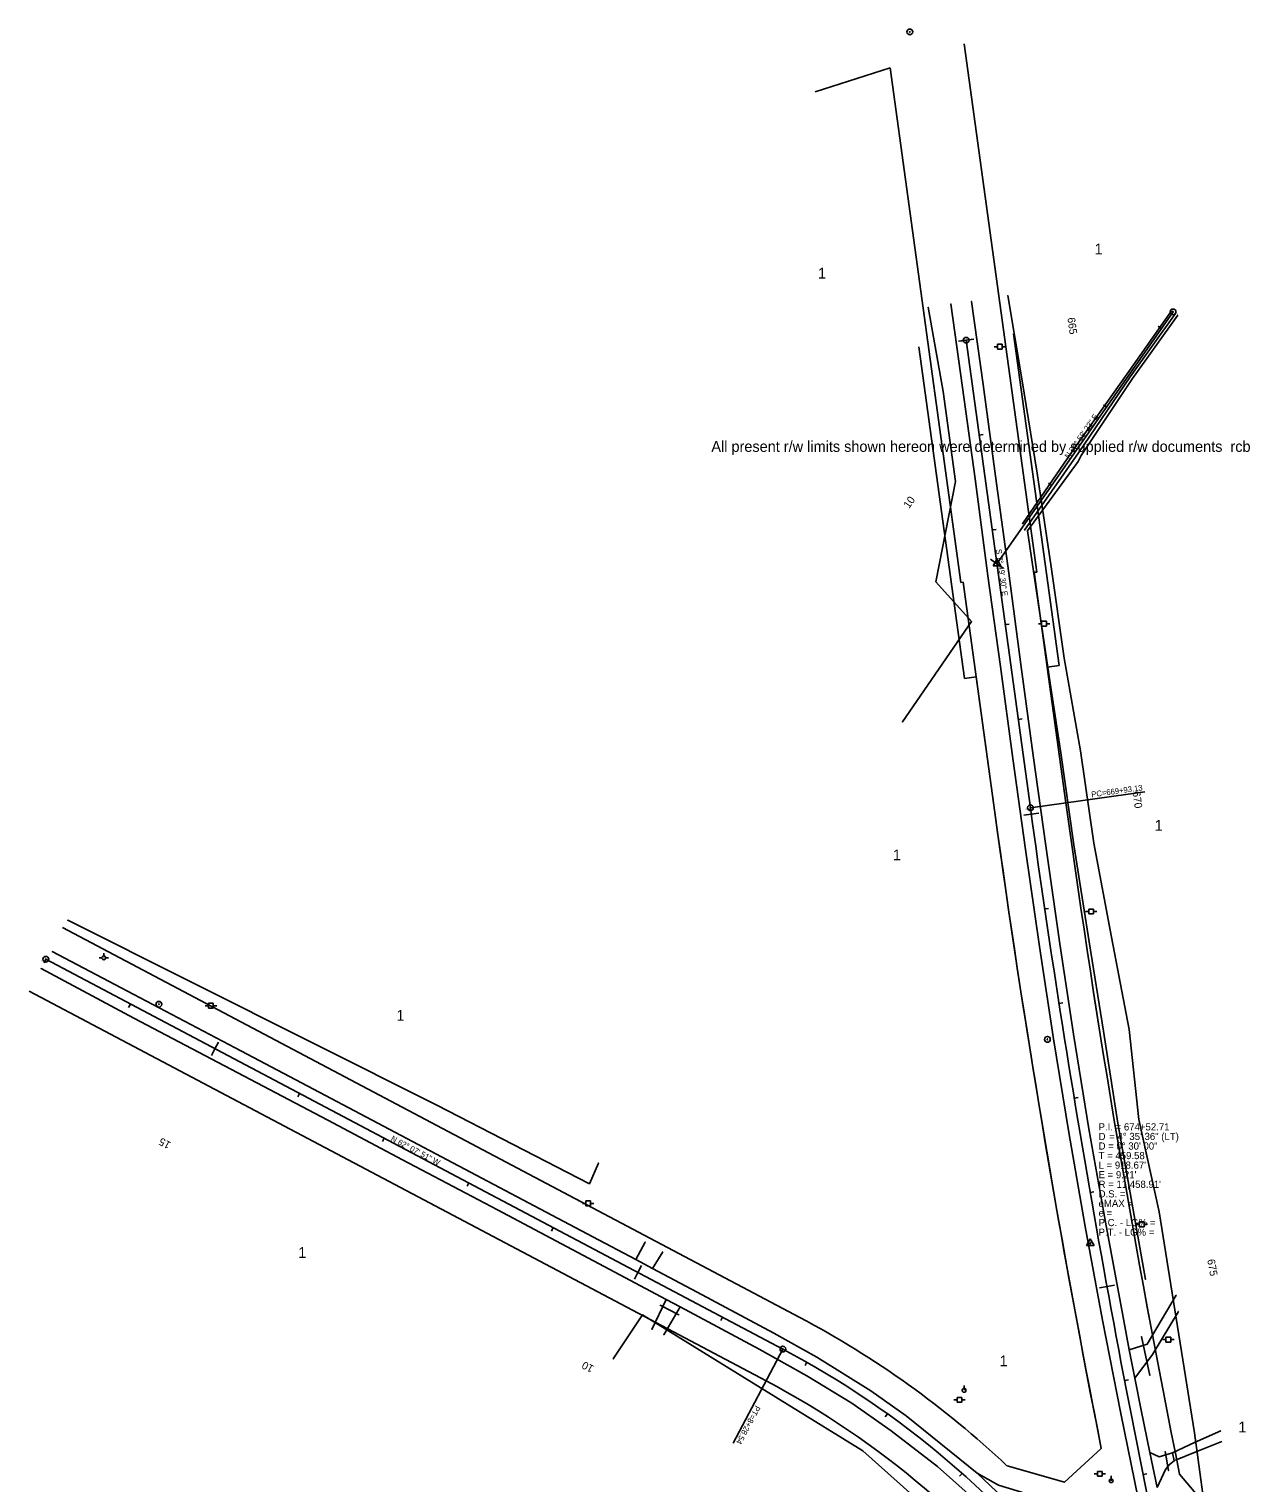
# Model space of a CAD drawing. Extents: x 2519952 to 2531965, y 848341 to 887632.
# Drawn here: x 2529614 to 2530890, y 853383 to 854902 of the extents above; entities that cross this region are included whole.
import ezdxf

# ---------------------------------------------------------------- set-up
doc = ezdxf.new("R2010")
doc.units = 0
for name, color, linetype in [('RD_EX_DR_Pipe', 7, 'Continuous'), ('RD_EX_Driveway', 7, 'Continuous'), ('RD_EX_DV_Prop', 7, 'Continuous'), ('RD_EX_DV_TX_Prop', 7, 'Continuous'), ('RD_EX_Fence_Other', 7, 'Continuous'), ('RD_EX_H2O', 7, 'Continuous'), ('RD_EX_Road', 7, 'Continuous'), ('RD_EX_RW', 7, 'Continuous'), ('RD_EX_RW_TX', 7, 'Continuous'), ('RD_EX_UT', 7, 'Continuous'), ('RD_EX_VEG', 7, 'Continuous'), ('RD_HC_Cl', 7, 'Continuous'), ('RD_HC_Data', 7, 'Continuous'), ('RD_HC_Data_Tic', 7, 'Continuous'), ('RD_HC_Survey_txCode', 7, 'Continuous'), ('RD_HC_TX_Sta50', 7, 'Continuous'), ('RD_HC_txCode', 7, 'Continuous'), ('RD_SMD_Locator', 7, 'Continuous')]:
    doc.layers.add(name, color=color, linetype=linetype)

msp = doc.modelspace()

# ---------------------------------------------------------------- linework, layer by layer
at = {"layer": 'RD_EX_DR_Pipe'}
for p, q in [((2530293.2, 853558.5), (2530273.6, 853568.5)), ((2530785.4, 853495.1), (2530776.8, 853535.8)), ((2530805, 853395.7), (2530801.5, 853415.5))]:
    msp.add_line(p, q, dxfattribs=at)
at = {"layer": 'RD_EX_Driveway'}
for p, q in [((2530258, 853634.6), (2530248.1, 853616.3)), ((2530265.6, 853606.8), (2530276.3, 853624.2)), ((2530280, 853574.6), (2530265, 853543.2)), ((2530294.6, 853567), (2530277.3, 853537.6))]:
    msp.add_line(p, q, dxfattribs=at)
for points in [[(2530763.7, 853522), (2530782.6, 853527.7), (2530813, 853578.9)], [(2530769.8, 853492.4), (2530788.3, 853516.9), (2530815.2, 853562.1)], [(2530809.1, 853414.4), (2530832.1, 853424.9), (2530859.4, 853437.3)], [(2530812.2, 853406.7), (2530832.7, 853414.9), (2530860.6, 853426.1)], [(2530793.2, 853378), (2530801.7, 853396.7), (2530805.9, 853402), (2530810.8, 853405.8), (2530809, 853414.1), (2530795.2, 853410.2), (2530785.5, 853414.5)]]:
    msp.add_lwpolyline(points, dxfattribs=at)
at = {"layer": 'RD_EX_DV_Prop'}
for p, q in [((2530591.2, 854886.7), (2530667.1, 854334.8)), ((2530435.6, 854836.5), (2530513.9, 854861.8)), ((2530513.9, 854861.8), (2530587.8, 854323.9)), ((2530664.6, 854334.5), (2530667.1, 854334.8)), ((2530664.6, 854334.5), (2530697.7, 854093.6)), ((2530590.3, 854324.3), (2530587.8, 854323.9)), ((2530590.3, 854324.3), (2530623.4, 854083.4)), ((2530419.4, 853555.8), (2529649, 853963.2)), ((2530384.4, 853489.5), (2529614, 853896.9)), ((2530696.3, 853383.6), (2530734.6, 853418.9)), ((2530636.1, 853400.8), (2530696.3, 853383.6)), ((2530816.5, 853392), (2530873.2, 853325.3))]:
    msp.add_line(p, q, dxfattribs=at)
for centre, radius, start, end in [((2542013, 855648.7), 11421.7, 187.82505, 191.39527), ((2542013, 855648.7), 11496.7, 187.82505, 191.18314), ((2529955.5, 852678.5), 992.4, 46.7055, 62.1307), ((2529955.5, 852678.5), 917.4, 12.4185, 62.1307)]:
    msp.add_arc(centre, radius, start, end, dxfattribs=at)
at = {"layer": 'RD_EX_Fence_Other'}
msp.add_lwpolyline([(2530781, 853595.5), (2530751.8, 853758.9), (2530737.1, 853854.9), (2530721.9, 853948.2), (2530705.8, 854049.8), (2530692.2, 854145.7), (2530682.3, 854211.8), (2530657.5, 854377.9), (2530710.3, 854450.3), (2530710.3, 854450.3), (2530713.5, 854456.6), (2530767.2, 854537.2), (2530814.6, 854603.4)], dxfattribs=at)
at = {"layer": 'RD_EX_H2O'}
for points in [[(2530652.2, 854385.2), (2530707.4, 854465.2), (2530761.5, 854541.9), (2530808, 854607.9)], [(2530654.4, 854378.6), (2530710.8, 854459.4), (2530764.7, 854538.9), (2530812.1, 854605.1)]]:
    msp.add_lwpolyline(points, dxfattribs=at)
at = {"layer": 'RD_EX_Road'}
for p, q in [((2530589.4, 854527.6), (2530577.4, 854615)), ((2530611, 854530.8), (2530599.1, 854617.6)), ((2530624.2, 854435.1), (2530611, 854530.8)), ((2530602.7, 854432.2), (2530589.4, 854527.6)), ((2530616.2, 854330.7), (2530602.7, 854432.2)), ((2530637.9, 854333.6), (2530624.2, 854435.1)), ((2530650.7, 854238.3), (2530637.9, 854333.6)), ((2530629.4, 854236.2), (2530616.2, 854330.7)), ((2530642.3, 854139.9), (2530629.4, 854236.2)), ((2530663.5, 854143), (2530650.7, 854238.3)), ((2530655.3, 854044.8), (2530642.3, 854139.9)), ((2530676.5, 854048.6), (2530663.5, 854143)), ((2530670, 853943.5), (2530655.3, 854044.8)), ((2530691.4, 853946.2), (2530676.5, 854048.6)), ((2530684.8, 853846.8), (2530670, 853943.5)), ((2530705.7, 853851.7), (2530691.4, 853946.2)), ((2530721.7, 853752.8), (2530705.7, 853851.7)), ((2530700.6, 853749.2), (2530684.8, 853846.8)), ((2530717.9, 853650.8), (2530700.6, 853749.2)), ((2530739.2, 853655.2), (2530721.7, 853752.8)), ((2530736, 853552.8), (2530717.9, 853650.8)), ((2530757.4, 853555.9), (2530739.2, 853655.2)), ((2530755.2, 853455.3), (2530736, 853552.8)), ((2530763.7, 853522), (2530757.4, 853555.9)), ((2530769.8, 853492.4), (2530763.7, 853522)), ((2530776.3, 853458.9), (2530769.8, 853492.4)), ((2530773, 853366.4), (2530755.2, 853455.3)), ((2530785.5, 853414.5), (2530776.3, 853458.9)), ((2530793.2, 853378), (2530785.5, 853414.5))]:
    msp.add_line(p, q, dxfattribs=at)
for points in [[(2530784.4, 853172.5), (2530741.9, 853238.2), (2530696.4, 853297.5), (2530665.4, 853333.2), (2530632.1, 853367.3), (2530604.8, 853393), (2530530.8, 853453), (2530493.8, 853479.2), (2530437.3, 853514.1), (2530392.4, 853539.3), (2530312.3, 853582.2), (2530265.6, 853606.8), (2530248.1, 853616.3), (2530203.3, 853640.1), (2530111.6, 853688.6), (2530014.7, 853739.6), (2529923.8, 853787.8), (2529829.3, 853837.4), (2529710.3, 853900.2), (2529638.2, 853938.2)], [(2530865.4, 852932.6), (2530846.1, 852991.5), (2530818.3, 853061.6), (2530788.3, 853122.1), (2530782.7, 853132.1), (2530724, 853225.4), (2530679.7, 853283.1), (2530649.1, 853318.6), (2530608, 853360.2), (2530563.3, 853399.9), (2530515, 853437.4), (2530473.9, 853466.1), (2530426.9, 853494.9), (2530377.2, 853522.5), (2530294.6, 853567), (2530280, 853574.6), (2530215.1, 853609.1), (2530103.7, 853668.1), (2530004.2, 853720.5), (2529926.3, 853762), (2529818.4, 853818.7), (2529723.5, 853868.7), (2529626.5, 853920.3)], [(2530773, 853366.4), (2530774.4, 853354.1), (2530767.3, 853348.8), (2530760, 853341.3), (2530677.6, 853365.2), (2530627.1, 853380.5), (2530604.8, 853393)]]:
    msp.add_lwpolyline(points, dxfattribs=at)
at = {"layer": 'RD_EX_RW'}
for p, q in [((2530642.9, 854583.8), (2530690.6, 854237.1)), ((2530543.9, 854570.2), (2530591.5, 854223.5)), ((2530678.2, 854235.4), (2530690.6, 854237.1)), ((2530678.2, 854235.4), (2530697.7, 854093.6)), ((2530591.5, 854223.5), (2530603.9, 854225.2)), ((2530603.9, 854225.2), (2530623.4, 854083.4)), ((2530419.4, 853555.8), (2529649, 853963.2)), ((2530419.4, 853555.8), (2529649, 853963.2)), ((2530384.4, 853489.5), (2529614, 853896.9)), ((2530873.2, 853325.3), (2530816.5, 853392))]:
    msp.add_line(p, q, dxfattribs=at)
msp.add_lwpolyline([(2530636.1, 853400.8), (2530696.3, 853383.6), (2530734.6, 853418.9), (2530731.4, 853435.4)], dxfattribs=at)
for centre, radius, start, end in [((2542012.7, 855648.6), 11421.4, 187.82505, 191.39535), ((2542012.7, 855648.6), 11496.4, 187.82505, 191.09941), ((2529955.5, 852678.5), 992.4, 46.7055, 62.1308), ((2529955.5, 852678.5), 917.4, 12.4185, 62.1308)]:
    msp.add_arc(centre, radius, start, end, dxfattribs=at)
at = {"layer": 'RD_EX_UT'}
for p, q in [((2530622.6, 854570.3), (2530626, 854570.3)), ((2530631, 854572.9), (2530626, 854572.9)), ((2530626, 854572.9), (2530626, 854567.9)), ((2530626, 854567.9), (2530631, 854567.9)), ((2530630.9, 854570.3), (2530634.6, 854570.3)), ((2530631, 854567.9), (2530631, 854572.9)), ((2530668.9, 854280.7), (2530672.3, 854280.7)), ((2530677.3, 854283.3), (2530672.3, 854283.3)), ((2530672.3, 854283.3), (2530672.3, 854278.3)), ((2530672.3, 854278.3), (2530677.3, 854278.3)), ((2530677.2, 854280.7), (2530680.9, 854280.7)), ((2530677.3, 854278.3), (2530677.3, 854283.3)), ((2530718.1, 853979.9), (2530721.6, 853979.9)), ((2530726.5, 853982.5), (2530721.5, 853982.5)), ((2530721.5, 853982.5), (2530721.5, 853977.5)), ((2530721.5, 853977.5), (2530726.5, 853977.5)), ((2530726.5, 853977.5), (2530726.5, 853982.5)), ((2530726.5, 853979.9), (2530730.1, 853979.9)), ((2529687.1, 853931.6), (2529690, 853931.6)), ((2529692, 853936.6), (2529692, 853933.6)), ((2529694, 853931.6), (2529697.1, 853931.6)), ((2529798.1, 853881.5), (2529801.6, 853881.5)), ((2529806.5, 853884.1), (2529801.5, 853884.1)), ((2529801.5, 853884.1), (2529801.5, 853879.1)), ((2529801.5, 853879.1), (2529806.5, 853879.1)), ((2529806.5, 853879.1), (2529806.5, 853884.1)), ((2529806.5, 853881.5), (2529810.1, 853881.5)), ((2530192.4, 853674.9), (2530195.9, 853674.9)), ((2530200.9, 853677.5), (2530195.9, 853677.5)), ((2530195.9, 853677.5), (2530195.9, 853672.5)), ((2530195.9, 853672.5), (2530200.9, 853672.5)), ((2530200.8, 853674.9), (2530204.4, 853674.9)), ((2530200.9, 853672.5), (2530200.9, 853677.5)), ((2530770.9, 853653.1), (2530774.4, 853653.1)), ((2530779.3, 853655.6), (2530774.3, 853655.6)), ((2530774.3, 853655.6), (2530774.3, 853650.6)), ((2530774.3, 853650.6), (2530779.3, 853650.6)), ((2530779.3, 853650.6), (2530779.3, 853655.6)), ((2530779.3, 853653.1), (2530782.9, 853653.1)), ((2530798.8, 853532.6), (2530802.3, 853532.6)), ((2530807.2, 853535.1), (2530802.2, 853535.1)), ((2530802.2, 853535.1), (2530802.2, 853530.1)), ((2530802.2, 853530.1), (2530807.2, 853530.1)), ((2530807.2, 853530.1), (2530807.2, 853535.1)), ((2530807.2, 853532.6), (2530810.8, 853532.6)), ((2530591.2, 853479.6), (2530591.2, 853484.6)), ((2530580.5, 853469.6), (2530584, 853469.6)), ((2530588.9, 853472.1), (2530583.9, 853472.1)), ((2530583.9, 853472.1), (2530583.9, 853467.1)), ((2530583.9, 853467.1), (2530588.9, 853467.1)), ((2530588.8, 853469.6), (2530592.5, 853469.6)), ((2530588.9, 853467.1), (2530588.9, 853472.1)), ((2530727.1, 853392.3), (2530730.6, 853392.3)), ((2530735.6, 853394.9), (2530730.6, 853394.9)), ((2530730.6, 853394.9), (2530730.6, 853389.9)), ((2530735.5, 853392.3), (2530739.1, 853392.3)), ((2530735.6, 853389.9), (2530735.6, 853394.9)), ((2530730.6, 853389.9), (2530735.6, 853389.9)), ((2530744.9, 853385.1), (2530744.9, 853390.1))]:
    msp.add_line(p, q, dxfattribs=at)
for centre in [(2529692, 853931.6), (2530591.2, 853479.6), (2530744.9, 853385.1)]:
    msp.add_circle(centre, 2, dxfattribs=at)
at = {"layer": 'RD_EX_VEG'}
for points in [[(2530846.5, 853330.1), (2530832, 853435), (2530795, 853666.3), (2530773.7, 853762.8), (2530763.7, 853856.8), (2530745.4, 853953.1), (2530726.7, 854051.6), (2530713, 854148), (2530695.8, 854244.8), (2530682.3, 854340.3), (2530667.5, 854438.1), (2530651.6, 854536.8), (2530636.9, 854623.8)], [(2530526.7, 854178.2), (2530599, 854283), (2530561.7, 854324.7), (2530582.2, 854429.5), (2530569.4, 854523.4), (2530553.8, 854611.5)], [(2530209.3, 853717.1), (2530199.7, 853695.5), (2530040.3, 853777.7), (2529654.4, 853970.9)], [(2530820.3, 852991.2), (2530765.5, 853118.8), (2530674.3, 853267.5), (2530658.5, 853261.6), (2530485.3, 853416.3), (2530406.2, 853465.1), (2530255.2, 853558.4), (2530224.6, 853512.5)]]:
    msp.add_lwpolyline(points, dxfattribs=at)
at = {"layer": 'RD_HC_Cl'}
for p, q in [((2530625.5, 854343.5), (2530809.6, 854606.7)), ((2530593.4, 854577), (2530660.5, 854088.5)), ((2530401.9, 853522.7), (2529631.5, 853930.1))]:
    msp.add_line(p, q, dxfattribs=at)
for centre, radius, start, end in [((2542012.7, 855648.6), 11458.9, 187.82505, 192.41848), ((2529955.5, 852678.5), 954.9, 12.4185, 62.1308)]:
    msp.add_arc(centre, radius, start, end, dxfattribs=at)
at = {"layer": 'RD_HC_Data'}
for p, q in [((2530621.5, 854341.2), (2530625.5, 854348.1)), ((2530621.5, 854341.2), (2530629.5, 854341.2)), ((2530625.5, 854348.1), (2530629.5, 854341.2)), ((2530660.5, 854088.5), (2530780.3, 854105)), ((2530719.1, 853630.9), (2530723.1, 853637.8)), ((2530723.1, 853637.8), (2530727.1, 853630.9)), ((2530719.1, 853630.9), (2530727.1, 853630.9)), ((2530401.9, 853522.7), (2530349.9, 853424.3))]:
    msp.add_line(p, q, dxfattribs=at)
for centre, radius in [((2530534.5, 854899.3), 3), ((2530534.5, 854899.3), 0.282), ((2530809.6, 854606.7), 3), ((2530809.6, 854606.7), 0.282), ((2530593.4, 854577), 3), ((2530593.4, 854577), 0.282), ((2530625.5, 854343.5), 0.529), ((2530660.5, 854088.5), 3), ((2530660.5, 854088.5), 0.282), ((2529631.5, 853930.1), 3), ((2529631.5, 853930.1), 0.282), ((2529749.7, 853883.1), 3), ((2529749.7, 853883.1), 0.282), ((2530678.3, 853846.4), 3), ((2530678.3, 853846.4), 0.282), ((2530723.1, 853633.2), 0.529), ((2530401.9, 853522.7), 3), ((2530401.9, 853522.7), 0.282)]:
    msp.add_circle(centre, radius, dxfattribs=at)
at = {"layer": 'RD_HC_Data_Tic'}
for p, q in [((2530797.4, 854589.3), (2530794.2, 854591.6)), ((2530593.4, 854577), (2530585.5, 854576)), ((2530593.4, 854577), (2530601.3, 854578.1)), ((2530740.1, 854507.4), (2530736.8, 854509.6)), ((2530607, 854478), (2530611, 854478.5)), ((2530682.8, 854425.4), (2530679.5, 854427.7)), ((2530620.6, 854378.9), (2530624.6, 854379.4)), ((2530625.5, 854343.5), (2530618.9, 854348.1)), ((2530625.5, 854343.5), (2530632, 854338.9)), ((2530634.2, 854279.8), (2530638.2, 854280.4)), ((2530647.8, 854180.8), (2530651.8, 854181.3)), ((2530661.5, 854081.7), (2530653.5, 854080.6)), ((2530661.5, 854081.7), (2530669.4, 854082.8)), ((2530675.6, 853982.7), (2530679.5, 853983.3)), ((2529631.5, 853930.1), (2529629.6, 853926.5)), ((2529719.9, 853883.3), (2529718, 853879.8)), ((2530690.5, 853883.8), (2530694.5, 853884.4)), ((2529808.3, 853836.6), (2529804.6, 853829.5)), ((2529808.3, 853836.6), (2529812.1, 853843.6)), ((2529896.7, 853789.8), (2529894.8, 853786.3)), ((2530706.4, 853785.1), (2530710.3, 853785.7)), ((2529985.1, 853743.1), (2529983.3, 853739.5)), ((2530073.5, 853696.3), (2530071.7, 853692.8)), ((2530723.1, 853686.5), (2530727, 853687.2)), ((2530161.9, 853649.6), (2530160.1, 853646)), ((2530250.3, 853602.8), (2530254.1, 853609.9)), ((2530250.3, 853602.8), (2530246.6, 853595.8)), ((2530740.6, 853588), (2530748.5, 853589.5)), ((2530740.6, 853588), (2530732.7, 853586.6)), ((2530338.7, 853556.1), (2530336.9, 853552.6)), ((2530426.9, 853509), (2530425, 853505.5)), ((2530759, 853489.8), (2530763, 853490.5)), ((2530511.1, 853455.1), (2530508.8, 853451.9)), ((2530589.3, 853392.8), (2530586.6, 853389.8)), ((2530778.3, 853391.6), (2530782.2, 853392.4))]:
    msp.add_line(p, q, dxfattribs=at)
at = {"layer": 'RD_SMD_Locator'}
for centre in [(2530534.5, 854899.3), (2530636.9, 854623.8), (2530553.8, 854611.5), (2530577.4, 854615), (2530599.1, 854617.6), (2530808, 854607.9), (2530809.6, 854606.7), (2530812.1, 854605.1), (2530814.6, 854603.4), (2530593.4, 854577), (2530611, 854530.8), (2530651.6, 854536.8), (2530761.5, 854541.9), (2530764.7, 854538.9), (2530767.2, 854537.2), (2530569.4, 854523.4), (2530589.4, 854527.6), (2530707.4, 854465.2), (2530710.8, 854459.4), (2530713.5, 854456.6), (2530710.3, 854450.3), (2530710.3, 854450.3), (2530582.2, 854429.5), (2530602.7, 854432.2), (2530624.2, 854435.1), (2530667.5, 854438.1), (2530652.2, 854385.2), (2530654.4, 854378.6), (2530657.5, 854377.9), (2530625.5, 854343.5), (2530637.9, 854333.6), (2530682.3, 854340.3), (2530561.7, 854324.7), (2530616.2, 854330.7), (2530599, 854283), (2530695.8, 854244.8), (2530629.4, 854236.2), (2530650.7, 854238.3), (2530682.3, 854211.8), (2530526.7, 854178.2), (2530642.3, 854139.9), (2530663.5, 854143), (2530692.2, 854145.7), (2530713, 854148), (2530660.5, 854088.5), (2530655.3, 854044.8), (2530676.5, 854048.6), (2530705.8, 854049.8), (2530726.7, 854051.6), (2529654.4, 853970.9), (2529638.2, 853938.2), (2530670, 853943.5), (2530691.4, 853946.2), (2530721.9, 853948.2), (2530745.4, 853953.1), (2529631.5, 853930.1), (2529626.5, 853920.3), (2529710.3, 853900.2), (2529749.7, 853883.1), (2529723.5, 853868.7), (2530705.7, 853851.7), (2530737.1, 853854.9), (2530763.7, 853856.8), (2529829.3, 853837.4), (2530678.3, 853846.4), (2530684.8, 853846.8), (2529818.4, 853818.7), (2529923.8, 853787.8), (2530040.3, 853777.7), (2529926.3, 853762), (2530751.8, 853758.9), (2530773.7, 853762.8), (2530700.6, 853749.2), (2530721.7, 853752.8), (2530014.7, 853739.6), (2530004.2, 853720.5), (2530209.3, 853717.1), (2530199.7, 853695.5), (2530111.6, 853688.6), (2530103.7, 853668.1), (2530795, 853666.3), (2530717.9, 853650.8), (2530739.2, 853655.2), (2530203.3, 853640.1), (2530258, 853634.6), (2530276.3, 853624.2), (2530723.1, 853633.2), (2530215.1, 853609.1), (2530248.1, 853616.3), (2530248.1, 853616.3), (2530265.6, 853606.8), (2530265.6, 853606.8), (2530781, 853595.5), (2530280, 853574.6), (2530280, 853574.6), (2530312.3, 853582.2), (2530813, 853578.9), (2530255.2, 853558.4), (2530273.6, 853568.5), (2530293.2, 853558.5), (2530294.6, 853567), (2530294.6, 853567), (2530815.2, 853562.1), (2530265, 853543.2), (2530736, 853552.8), (2530757.4, 853555.9), (2530277.3, 853537.6), (2530392.4, 853539.3), (2530776.8, 853535.8), (2530377.2, 853522.5), (2530401.9, 853522.7), (2530437.3, 853514.1), (2530763.7, 853522), (2530763.7, 853522), (2530782.6, 853527.7), (2530788.3, 853516.9), (2530224.6, 853512.5), (2530426.9, 853494.9), (2530769.8, 853492.4), (2530769.8, 853492.4), (2530785.4, 853495.1), (2530493.8, 853479.2), (2530406.2, 853465.1), (2530473.9, 853466.1), (2530530.8, 853453), (2530755.2, 853455.3), (2530776.3, 853458.9), (2530515, 853437.4), (2530859.4, 853437.3), (2530832, 853435), (2530832.1, 853424.9), (2530860.6, 853426.1), (2530485.3, 853416.3), (2530785.5, 853414.5), (2530785.5, 853414.5), (2530795.2, 853410.2), (2530801.5, 853415.5), (2530809, 853414.1), (2530809.1, 853414.4), (2530812.2, 853406.7), (2530832.7, 853414.9), (2530563.3, 853399.9), (2530604.8, 853393), (2530604.8, 853393), (2530801.7, 853396.7), (2530805, 853395.7), (2530805.9, 853402), (2530810.8, 853405.8)]:
    msp.add_circle(centre, 0.001, dxfattribs=at)

# ---------------------------------------------------------------- texts
at = {"layer": 'RD_EX_DV_TX_Prop'}
for p in [(2530727.6, 854666.8), (2530438.6, 854641.5), (2530790.4, 854064.4), (2530516.8, 854033.5), (2529998, 853865.9), (2529895.3, 853618), (2530628.3, 853504.7), (2530877.9, 853435.6)]:
    msp.add_text('1', height=11.3, dxfattribs=at).set_placement(p)
at = {"layer": 'RD_EX_RW_TX'}
msp.add_text('All present r/w limits shown hereon were determined by supplied r/w documents  rcb', height=11.317, dxfattribs=at).set_placement((2530327.1, 854460.4))
at = {"layer": 'RD_EX_UT'}
msp.add_text('T', height=2, dxfattribs=at).set_placement((2529691.4, 853930.5))
at = {"layer": 'RD_HC_Data'}
for s, rotation, p in [('PC=669+93.13', 7.8251, (2530724.6, 854099.3)), ('PT=8+28.54', 242.1308, (2530373.3, 853464.3))]:
    msp.add_text(s, height=6, rotation=rotation, dxfattribs=at).set_placement(p)
at = {"layer": 'RD_HC_Survey_txCode'}
for s, rotation, p in [('N 34%%d 58\' 23" E', 55.0271, (2530700.7, 854452.8)), ('S 7%%d 49\' 30" E', 277.8251, (2530624.4, 854358.4)), ('N 62%%d 07\' 51" W', 332.1308, (2529991.5, 853740.8))]:
    msp.add_text(s, height=6, rotation=rotation, dxfattribs=at).set_placement(p)
for s, p in [('P.I. = 674+52.71', (2530731.8, 853751.2)), ('D', (2530731.8, 853741.2)), ('    = 4%%d 35\' 36" (LT)', (2530731.8, 853741.2)), ("T = 459.58'", (2530731.8, 853721.2)), ('D = 0%%d 30\' 00"', (2530731.8, 853731.2)), ("L = 918.67'", (2530731.8, 853711.2)), ("E = 9.21'", (2530731.8, 853701.2)), ("R = 11,458.91'", (2530731.8, 853691.2)), ('D.S. = ', (2530731.8, 853681.2)), ('eMAX = ', (2530731.8, 853671.2)), ('e = ', (2530731.8, 853661.2)), ('P.C. - LG% = ', (2530731.8, 853651.2)), ('P.T. - LG% = ', (2530731.8, 853641.2))]:
    msp.add_text(s, height=7.5, dxfattribs=at).set_placement(p)
at = {"layer": 'RD_HC_TX_Sta50'}
for s, rotation, p in [('665', 277.8251, (2530699.2, 854600.4)), ('10', 55.0271, (2530533.7, 854400.6)), ('670', 277.8594, (2530767.3, 854105.1)), ('15', 152.1308, (2529762.9, 853738.4)), ('675', 280.3595, (2530845.3, 853616)), ('10', 152.1308, (2530205, 853504.7))]:
    msp.add_text(s, height=8, rotation=rotation, dxfattribs=at).set_placement(p)
at = {"layer": 'RD_HC_txCode'}
for s, p in [('CP 5 PSC', (2530530.9, 854897.3)), ('5', (2530534.2, 854900.3)), ('45', (2530808.9, 854607.7)), ('POT 13+21.28', (2530805, 854604.7)), ('10', (2530592.9, 854578)), ('POT 665+00.00', (2530587.5, 854575)), ('PI 10+00.00', (2530621.5, 854341.5)), ('44', (2530624.8, 854344.5)), ('11', (2530660.4, 854089.5)), ('PC 669+93.13', (2530655.6, 854086.5)), ('POT 17+00.00', (2529626.4, 853928.1)), ('20', (2529630.7, 853931.1)), ('CP 8 MSC', (2529746.1, 853881.1)), ('8', (2529749.4, 853884.1)), ('4', (2530678, 853847.4)), ('CP 4 PSC', (2530674.7, 853844.4)), ('12', (2530722.6, 853634.2)), ('PI 674+52.71', (2530718.8, 853631.2)), ('PT 8+28.54', (2530397.6, 853520.7)), ('18', (2530401.5, 853523.7))]:
    msp.add_text(s, height=1, dxfattribs=at).set_placement(p)

doc.saveas('drawing.dxf')
